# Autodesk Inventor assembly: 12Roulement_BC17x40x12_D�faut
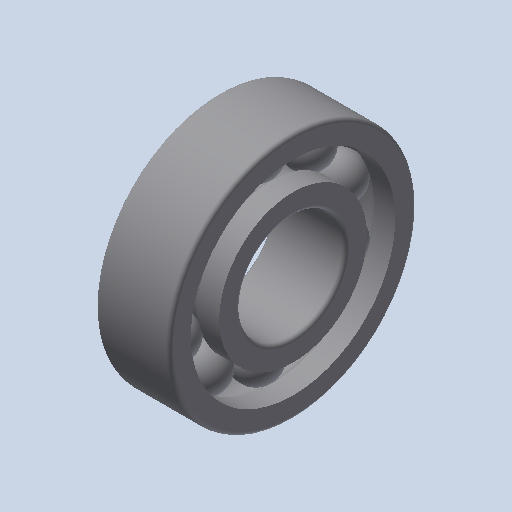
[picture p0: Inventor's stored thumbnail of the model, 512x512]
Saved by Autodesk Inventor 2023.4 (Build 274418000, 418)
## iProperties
Created: 2011-01
Part Number: 12Roulement_BC17x40x12_D�faut
Document SubType Name: Assembly
Designer: eric
Mass: 8.37238 g
Surface Area: 70.5503 cm^2
Volume: 8.37238 cm^3
Density: 1 g/cm^3
Author: eric
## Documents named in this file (4)
- C:\Users\bruno\Documents\1-Cours-2024-25\TSsI\7-Dynamique\chariot de golf\chariot_de_golf\chariot_de_golf_trolem\12Roulement_BC17x40x12_Defaut.iam
- C:\Users\bruno\Documents\1-Cours-2024-25\TSsI\7-Dynamique\chariot de golf\chariot_de_golf\chariot_de_golf_trolem\Roulement_r1rb_Eroul40_Defaut.ipt
- C:\Users\bruno\Documents\1-Cours-2024-25\TSsI\7-Dynamique\chariot de golf\chariot_de_golf\chariot_de_golf_trolem\Roulement_r1rb_Bext40_Defaut.ipt
- C:\Users\bruno\Documents\1-Cours-2024-25\TSsI\7-Dynamique\chariot de golf\chariot_de_golf\chariot_de_golf_trolem\Roulement_r1rb_Bint40_Defaut.ipt
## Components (12 placed, 3 different names)
1. Roulement_r1rb_Eroul40_Defaut:1
2. Roulement_r1rb_Eroul40_Defaut:2
3. Roulement_r1rb_Eroul40_Defaut:3
4. Roulement_r1rb_Bext40_Defaut:1
5. Roulement_r1rb_Eroul40_Defaut:4
6. Roulement_r1rb_Eroul40_Defaut:5
7. Roulement_r1rb_Eroul40_Defaut:6
8. Roulement_r1rb_Eroul40_Defaut:7
9. Roulement_r1rb_Bint40_Defaut:1
10. Roulement_r1rb_Eroul40_Defaut:8
11. Roulement_r1rb_Eroul40_Defaut:9
12. Roulement_r1rb_Eroul40_Defaut:10
